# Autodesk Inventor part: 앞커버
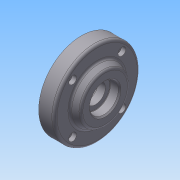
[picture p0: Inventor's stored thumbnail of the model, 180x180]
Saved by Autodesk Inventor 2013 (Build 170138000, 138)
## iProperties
Company: 한국ATC센터
Created: 2015-12
Part Number: 앞커버
Document SubType Name: Modeling
Designer: 앞커버
Density: 2.71 g/cm^3
Mass: 114.339 g
Surface Area: 117.889 cm^2
Volume: 42.1916 cm^3
Material: 알루미늄 6061
Author: mdu
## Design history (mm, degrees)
sketch "스케치1"
  geometry: L1 (-11.5, 0)-(11.5, 0); L2 (11.5, 0)-(11.5, 22.5); L3 (11.5, 22.5)-(6.5, 22.5); L4 (6.5, 22.5)-(6.5, 32.5); L5 (6.5, 32.5)-(-5.5, 32.5); L6 (-5.5, 32.5)-(-5.5, 21); L7 (-5.5, 21)-(-11.5, 18.202); L8 (-11.5, 18.202)-(-11.5, 0); 2 further points
  constraints: 16 end point, 3 parallel, 3 perpendicular, 1 coincident, 1 horizontal, 1 midpoint
  dimensions: "d0" = 23 distance of L1.start L1.end; "d1" = 65 diameter of L5 L1; "d2" = 45 diameter of L3 L1; "d3" = 42 diameter of L6.end L1; "d4" = 115 deg angle of L7 L6; "d5" = 12 distance of L4.end L5.end; "d6" = 5 distance of L2.end L3.end
revolve "회전1" sketch "스케치1" stored, may be unused: angle "d7" = 90 deg
sketch "스케치2"
  geometry: L1 (0, 0)-(32.5, 0); L2 (0, 0)-(18.738, 18.738); 1 further point
  constraints: 4 end point, 1 horizontal, 1 horizontal alignment, 1 other
  dimensions: "d8" = 45 deg angle of L1 L2; "d9" = 26.5 distance of L1.start L2.end
hole "구멍1" sketch "스케치2" at (18.738, 18.738) diameter "d10" = 3.4; stored, may be unused: countersink angle "d14" = 90 deg, drill point angle "d16" = 118 deg; dims "d11" = 6, "d12" = 6, "d13" = 3.3, "d15" = 8
fillet "모깎기1" dims "d20" = 2
hole "구멍2" diameter "d23" = 15; stored, may be unused: countersink angle "d27" = 90 deg, drill point angle "d29" = 118 deg; dims "d21" = 10, "d22" = 10, "d24" = 6, "d25" = 32, "d26" = 10, "d28" = 8
hole "구멍3" diameter "d32" = 22; stored, may be unused: countersink angle "d36" = 90 deg, drill point angle "d38" = 0 deg; dims "d30" = 10, "d31" = 10, "d33" = 6, "d34" = 32, "d35" = 10, "d37" = 7.3
chamfer "모따기1" distance "d39" = 1; stored, may be unused: second distance "d40" = 2, angle "d41" = 45 deg
fillet "모깎기2" dims "d42" = 0.3
node "솔리드1"
pattern_circular "원형 패턴1" dims angle "d18" = 360 deg
